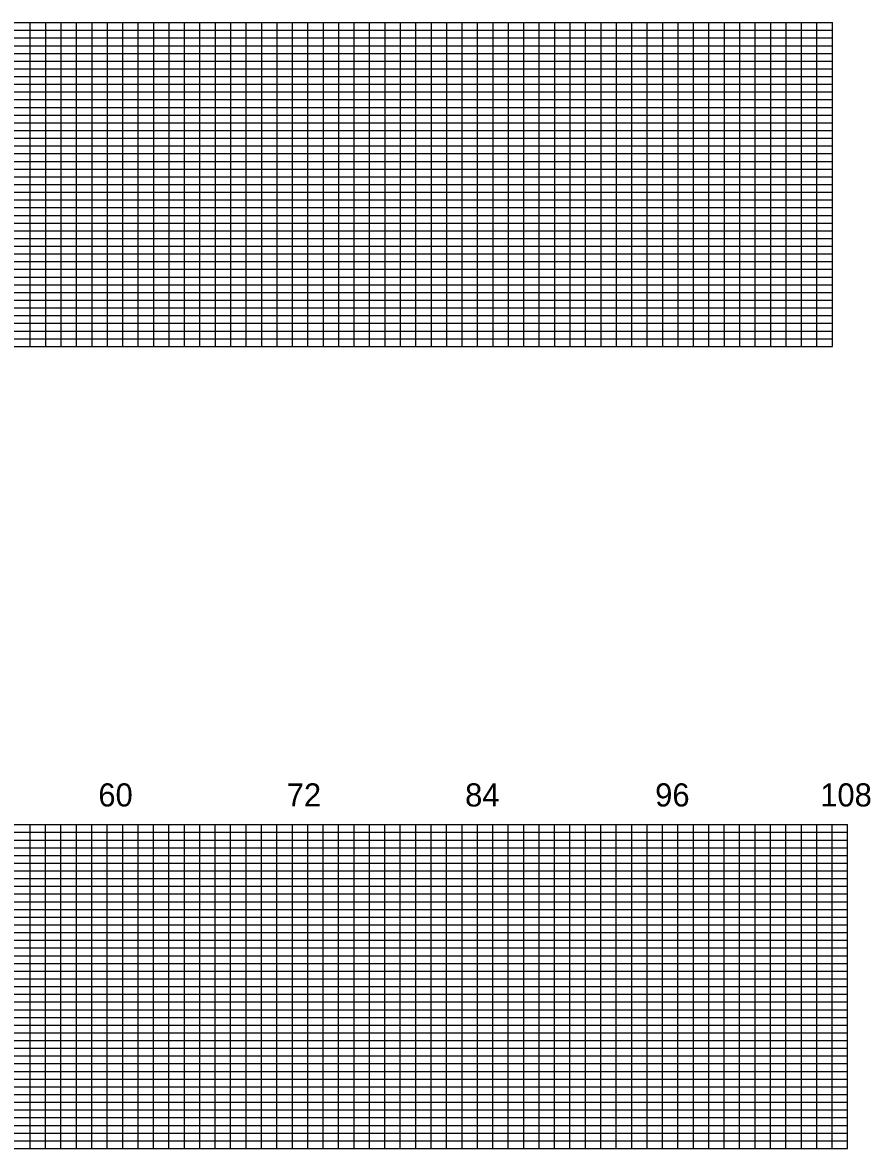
# Model space of a CAD drawing. Extents: x 1914168 to 1925341, y 720939 to 777401.
# Drawn here: x 1917153 to 1919902, y 770864 to 774514 of the extents above; entities that cross this region are included whole.
import ezdxf

# ---------------------------------------------------------------- set-up
doc = ezdxf.new("R2010")
doc.units = 0
doc.layers.add('RD_PD_WallFill', color=7, linetype='Continuous')

msp = doc.modelspace()

# ---------------------------------------------------------------- linework, layer by layer
at = {"layer": 'RD_PD_WallFill'}
for p, q in [((1914428, 774514.1), (1919778, 774514.2)), ((1917178, 773464.2), (1917178, 774514.2)), ((1917228, 773464.2), (1917228, 774514.2)), ((1917278, 773464.2), (1917278, 774514.2)), ((1917328, 773464.2), (1917328, 774514.2)), ((1917378, 773464.2), (1917378, 774514.2)), ((1917428, 773464.2), (1917428, 774514.2)), ((1917478, 773464.2), (1917478, 774514.2)), ((1917528, 773464.1), (1917528, 774514.2)), ((1917578, 773464.2), (1917578, 774514.2)), ((1917628, 773464.2), (1917628, 774514.2)), ((1917678, 773464.2), (1917678, 774514.2)), ((1917728, 773464.2), (1917728, 774514.2)), ((1917778, 773464.2), (1917778, 774514.2)), ((1917828, 773464.1), (1917828, 774514.2)), ((1917878, 773464.1), (1917878, 774514.2)), ((1917928, 773464.2), (1917928, 774514.2)), ((1917978, 773464.2), (1917978, 774514.2)), ((1918028, 773464.2), (1918028, 774514.2)), ((1918078, 773464.2), (1918078, 774514.2)), ((1918128, 773464.2), (1918128, 774514.2)), ((1918178, 773464.2), (1918178, 774514.2)), ((1918228, 773464.2), (1918228, 774514.2)), ((1918278, 773464.2), (1918278, 774514.2)), ((1918328, 773464.2), (1918328, 774514.2)), ((1918378, 773464.2), (1918378, 774514.2)), ((1918428, 773464.2), (1918428, 774514.2)), ((1918478, 773464.2), (1918478, 774514.2)), ((1918528, 773464.2), (1918528, 774514.2)), ((1918578, 773464.2), (1918578, 774514.2)), ((1918628, 773464.2), (1918628, 774514.2)), ((1918678, 773464.2), (1918678, 774514.2)), ((1918728, 773464.2), (1918728, 774514.2)), ((1918778, 773464.2), (1918778, 774514.2)), ((1918828, 773464.2), (1918828, 774514.2)), ((1918878, 773464.2), (1918878, 774514.2)), ((1918928, 773464.2), (1918928, 774514.2)), ((1918978, 773464.2), (1918978, 774514.2)), ((1919028, 773464.2), (1919028, 774514.2)), ((1919078, 773464.2), (1919078, 774514.2)), ((1919128, 773464.2), (1919128, 774514.2)), ((1919178, 773464.2), (1919178, 774514.2)), ((1919228, 773464.2), (1919228, 774514.2)), ((1919278, 773464.2), (1919278, 774514.2)), ((1919328, 773464.2), (1919328, 774514.2)), ((1919378, 773464.2), (1919378, 774514.2)), ((1919428, 773464.2), (1919428, 774514.2)), ((1919478, 773464.2), (1919478, 774514.2)), ((1919528, 773464.2), (1919528, 774514.2)), ((1919578, 773464.2), (1919578, 774514.2)), ((1919628, 773464.2), (1919628, 774514.2)), ((1919678, 773464.2), (1919678, 774514.2)), ((1919728, 773464.2), (1919728, 774514.2)), ((1919778, 773464.2), (1919778, 774514.2)), ((1914878, 774489.1), (1919778, 774489.1)), ((1914878, 774464.1), (1919778, 774464.1)), ((1914878, 774439.1), (1919778, 774439.1)), ((1914878, 774414.2), (1919778, 774414.1)), ((1914878, 774389.1), (1919778, 774389.2)), ((1914428, 774364.1), (1919778, 774364.1)), ((1914428, 774339.1), (1919778, 774339.1)), ((1914428, 774314.1), (1919778, 774314.2)), ((1914428, 774289.2), (1919778, 774289.1)), ((1914428, 774264.2), (1919778, 774264.2)), ((1914428, 774239.1), (1919778, 774239.1)), ((1914428, 774214.1), (1919778, 774214.1)), ((1914428, 774189.2), (1919778, 774189.1)), ((1914428, 774164.1), (1919778, 774164.1)), ((1914428, 774139.2), (1919778, 774139.1)), ((1914428, 774114.1), (1919778, 774114.1)), ((1914428, 774089.1), (1919778, 774089.2)), ((1914428, 774064.1), (1919778, 774064.1)), ((1914428, 774039.1), (1919778, 774039.2)), ((1914428, 774014.1), (1919778, 774014.1)), ((1914428, 773989.1), (1919778, 773989.1)), ((1914428, 773964.2), (1919778, 773964.1)), ((1914428, 773939.1), (1919778, 773939.1)), ((1914428, 773914.1), (1919778, 773914.1)), ((1914428, 773889.1), (1919778, 773889.1)), ((1914428, 773864.1), (1919778, 773864.2)), ((1914428, 773839.1), (1919778, 773839.1)), ((1914428, 773814.1), (1919778, 773814.1)), ((1914428, 773789.1), (1919778, 773789.1)), ((1914428, 773764.1), (1919778, 773764.1)), ((1914428, 773739.1), (1919778, 773739.1)), ((1914428, 773714.1), (1919778, 773714.1)), ((1914428, 773689.1), (1919778, 773689.1)), ((1914428, 773664.1), (1919778, 773664.1)), ((1914428, 773639.1), (1919778, 773639.1)), ((1914428, 773614.1), (1919778, 773614.1)), ((1914428, 773589.1), (1919778, 773589.1)), ((1914428, 773564.1), (1919778, 773564.1)), ((1914428, 773539.1), (1919778, 773539.1)), ((1914428, 773514.1), (1919778, 773514.1)), ((1914478, 773489.1), (1919778, 773489.1)), ((1914428, 773464.1), (1919778, 773464.1)), ((1914477.4, 771914.1), (1919827.4, 771914.1)), ((1917177.4, 770864.1), (1917177.4, 771914.1)), ((1917227.4, 770864.1), (1917227.4, 771914.1)), ((1917277.4, 770864.1), (1917277.4, 771914.1)), ((1917327.4, 770864.1), (1917327.4, 771914.1)), ((1917377.4, 770864.1), (1917377.4, 771914.1)), ((1917427.4, 770864.1), (1917427.4, 771914.1)), ((1917477.4, 770864.1), (1917477.4, 771914.1)), ((1917527.4, 770864.1), (1917527.4, 771914.1)), ((1917577.4, 770864.1), (1917577.4, 771914.1)), ((1917627.4, 770864.1), (1917627.4, 771914.1)), ((1917677.4, 770864.1), (1917677.4, 771914.1)), ((1917727.4, 770864.1), (1917727.4, 771914.1)), ((1917777.4, 770864.1), (1917777.4, 771914.1)), ((1917827.4, 770864.1), (1917827.4, 771914.1)), ((1917877.4, 770864.1), (1917877.4, 771914.1)), ((1917927.4, 770864.1), (1917927.4, 771914.1)), ((1917977.4, 770864.1), (1917977.4, 771914.1)), ((1918027.4, 770864.1), (1918027.4, 771914.1)), ((1918077.4, 770864.1), (1918077.4, 771914.1)), ((1918127.4, 770864.1), (1918127.4, 771914.1)), ((1918177.4, 770864.1), (1918177.4, 771914.1)), ((1918227.4, 770864.1), (1918227.4, 771914.1)), ((1918277.4, 770864.1), (1918277.4, 771914.1)), ((1918327.4, 770864.1), (1918327.4, 771914.1)), ((1918377.4, 770864.1), (1918377.4, 771914.1)), ((1918427.4, 770864.1), (1918427.4, 771914.1)), ((1918477.4, 770864.1), (1918477.4, 771914.1)), ((1918527.4, 770864.1), (1918527.4, 771914.1)), ((1918577.4, 770864.1), (1918577.4, 771914.1)), ((1918627.4, 770864.1), (1918627.4, 771914.1)), ((1918677.4, 770864.1), (1918677.4, 771914.1)), ((1918727.4, 770864.1), (1918727.4, 771914.1)), ((1918777.4, 770864.1), (1918777.4, 771914.1)), ((1918827.4, 770864.1), (1918827.4, 771914.1)), ((1918877.4, 770864.1), (1918877.4, 771914.1)), ((1918927.4, 770864.1), (1918927.4, 771914.1)), ((1918977.4, 770864.1), (1918977.4, 771914.1)), ((1919027.4, 770864.1), (1919027.4, 771914.1)), ((1919077.4, 770864.1), (1919077.4, 771914.1)), ((1919127.4, 770864.1), (1919127.4, 771914.1)), ((1919177.4, 770864.1), (1919177.4, 771914.1)), ((1919227.4, 770864.1), (1919227.4, 771914.1)), ((1919277.4, 770864.1), (1919277.4, 771914.1)), ((1919327.4, 770864.1), (1919327.4, 771914.1)), ((1919377.4, 770864.1), (1919377.4, 771914.1)), ((1919427.4, 770864.1), (1919427.4, 771914.1)), ((1919477.4, 770864.1), (1919477.4, 771914.1)), ((1919527.4, 770864.1), (1919527.4, 771914.1)), ((1919577.4, 770864.2), (1919577.4, 771914.1)), ((1919627.4, 770864.1), (1919627.4, 771914.1)), ((1919677.4, 770864.1), (1919677.4, 771914.1)), ((1919727.4, 770864.1), (1919727.4, 771914.1)), ((1919777.4, 770864.1), (1919777.4, 771914.1)), ((1919827.4, 770864.1), (1919827.4, 771914.1)), ((1914927.4, 771889.1), (1919827.4, 771889.1)), ((1914927.4, 771864.1), (1919827.4, 771864.1)), ((1914927.4, 771839.1), (1919827.4, 771839.1)), ((1914927.4, 771814.1), (1919827.4, 771814.1)), ((1914477.4, 771764.1), (1919827.4, 771764.1)), ((1914927.4, 771789.1), (1919827.4, 771789.1)), ((1914477.4, 771739.1), (1919827.4, 771739.1)), ((1914477.4, 771714.1), (1919827.4, 771714.1)), ((1914477.4, 771689.1), (1919827.4, 771689.1)), ((1914477.4, 771664.1), (1919827.4, 771664.1)), ((1914477.4, 771639.1), (1919827.4, 771639.1)), ((1914477.4, 771614.1), (1919827.4, 771614.1)), ((1914477.4, 771589.1), (1919827.4, 771589.1)), ((1914477.4, 771564.1), (1919827.4, 771564.1)), ((1914477.4, 771539.1), (1919827.4, 771539.1)), ((1914477.4, 771514.1), (1919827.4, 771514.1)), ((1914477.4, 771489.1), (1919827.4, 771489.1)), ((1914477.4, 771464.1), (1919827.4, 771464.1)), ((1914477.4, 771439.1), (1919827.4, 771439.1)), ((1914477.4, 771414.1), (1919827.4, 771414.1)), ((1914477.4, 771389.1), (1919827.4, 771389.1)), ((1914477.4, 771364.1), (1919827.4, 771364.1)), ((1914477.4, 771339.1), (1919827.4, 771339.1)), ((1914477.4, 771314.1), (1919827.4, 771314.1)), ((1914477.4, 771289.1), (1919827.4, 771289.1)), ((1914477.4, 771264.1), (1919827.4, 771264.1)), ((1914477.4, 771239.1), (1919827.4, 771239.1)), ((1914477.4, 771214.1), (1919827.4, 771214.1)), ((1914477.4, 771189.1), (1919827.4, 771189.1)), ((1914477.4, 771164.1), (1919827.4, 771164.1)), ((1914477.4, 771139.1), (1919827.4, 771139.1)), ((1914477.4, 771114.1), (1919827.4, 771114.1)), ((1914477.4, 771089.1), (1919827.4, 771089.1)), ((1914477.4, 771064.1), (1919827.4, 771064.1)), ((1914477.4, 771039.1), (1919827.4, 771039.1)), ((1914477.4, 771014.1), (1919827.4, 771014.1)), ((1914477.4, 770989.1), (1919827.4, 770989.1)), ((1914477.4, 770964.1), (1919827.4, 770964.1)), ((1914477.4, 770939.1), (1919827.4, 770939.1)), ((1914477.4, 770914.1), (1919827.4, 770914.1)), ((1914527.4, 770889.1), (1919827.4, 770889.1)), ((1914477.4, 770864.1), (1919827.4, 770864.1))]:
    msp.add_line(p, q, dxfattribs=at)

# ---------------------------------------------------------------- texts
for s, p in [('60', (1917398.5, 771972.8)), ('72', (1918009.2, 771972.8)), ('84', (1918587.5, 771972.8)), ('96', (1919203.6, 771972.8)), ('108', (1919738.6, 771972.8))]:
    msp.add_text(s, height=75, dxfattribs=at).set_placement(p)

doc.saveas('drawing.dxf')
